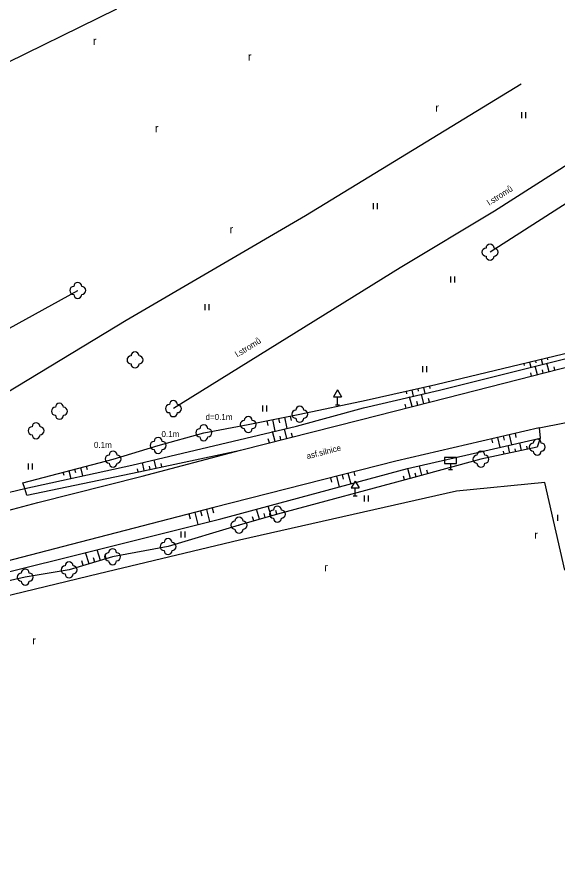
# Model space of a CAD drawing. Extents: x -544674 to -541478, y -1199076 to -1195527.
# Drawn here: x -543143.9 to -543076.3, y -1198278.6 to -1198172.4 of the extents above; entities that cross this region are included whole.
import ezdxf

# ---------------------------------------------------------------- set-up
doc = ezdxf.new("R2010")
doc.units = 0
for name, color, linetype in [('POMOC_POPIS', 7, 'Continuous'), ('ROZHRANÍ_PLOCH', 7, 'Continuous'), ('VÝŠKOPIS', 7, 'Continuous'), ('ZELEŇ', 7, 'Continuous'), ('ZN_DOPLŇKOVÉ', 7, 'Continuous'), ('ZN_KULTUR', 7, 'Continuous')]:
    doc.layers.add(name, color=color, linetype=linetype)

msp = doc.modelspace()

# ---------------------------------------------------------------- linework, layer by layer
at = {"layer": 'ROZHRANÍ_PLOCH'}
for points in [[(-543305.81, -1198268.45), (-543287.03, -1198267.34), (-543281.63, -1198266.75), (-543272.62, -1198265.24), (-543259.93, -1198262.7), (-543247.53, -1198260.01), (-543230.83, -1198255.93), (-543205.96, -1198249.68), (-543192.48, -1198246.27), (-543169.15, -1198240.29), (-543156.96, -1198237.13), (-543145.63, -1198234.19), (-543141.25, -1198233.03), (-543128.24, -1198229.71), (-543115.97, -1198226.49), (-543101.02, -1198222.68), (-543090.25, -1198219.95), (-543068.96, -1198214.5), (-543040.35, -1198207.27)], [(-543078.71, -1198223.67), (-543075.55, -1198223.08), (-543073.66, -1198223.03), (-543073.06, -1198223.47)], [(-543078.71, -1198223.67), (-543096.57, -1198227.83), (-543119.29, -1198233.63), (-543137.11, -1198238.27), (-543169.75, -1198246.75), (-543192.65, -1198252.45), (-543215.76, -1198258.44), (-543245.09, -1198265.54), (-543253.15, -1198267.41), (-543264.32, -1198269.8), (-543273.65, -1198271.57), (-543287.74, -1198273.53), (-543300.36, -1198274.19)]]:
    msp.add_lwpolyline(points, dxfattribs=at)
at = {"layer": 'VÝŠKOPIS'}
for points in [[(-543142.63, -1198232.09), (-543142.88, -1198231.28), (-543143.14, -1198230.54), (-543131.88, -1198227.59), (-543126.25, -1198225.89), (-543120.55, -1198224.3), (-543115, -1198223.27), (-543108.58, -1198221.98), (-543100.29, -1198220.25), (-543091.61, -1198218.29), (-543068.38, -1198212.71), (-543040.75, -1198205.87), (-543040.68, -1198206.39), (-543040.35, -1198207.27)], [(-543142.88, -1198231.28), (-543129.55, -1198228.33), (-543108.99, -1198223.46), (-543100.64, -1198221.19), (-543091.14, -1198218.96), (-543068.67, -1198213.36), (-543040.68, -1198206.39)], [(-543079.89, -1198215.47), (-543079.73, -1198216.12)], [(-543079.16, -1198215.3), (-543079.1, -1198215.55)], [(-543078.43, -1198215.12), (-543078.28, -1198215.75)], [(-543077.7, -1198214.95), (-543077.64, -1198215.2)], [(-543080.62, -1198215.65), (-543080.56, -1198215.91)], [(-543078.91, -1198217.05), (-543079.19, -1198215.98)], [(-543078.19, -1198216.86), (-543078.29, -1198216.44)], [(-543077.46, -1198216.68), (-543077.73, -1198215.62)], [(-543076.73, -1198216.49), (-543076.84, -1198216.07)], [(-543079.64, -1198217.23), (-543079.75, -1198216.81)], [(-543093.12, -1198218.63), (-543092.95, -1198219.38)], [(-543092.39, -1198218.47), (-543092.32, -1198218.76)], [(-543095.31, -1198219.13), (-543095.24, -1198219.43)], [(-543094.55, -1198221.04), (-543094.86, -1198219.83)], [(-543094.58, -1198218.96), (-543094.41, -1198219.73)], [(-543093.85, -1198218.8), (-543093.78, -1198219.1)], [(-543093.1, -1198220.67), (-543093.4, -1198219.49)], [(-543095.28, -1198221.23), (-543095.4, -1198220.74)], [(-543093.83, -1198220.86), (-543093.95, -1198220.38)], [(-543092.37, -1198220.49), (-543092.49, -1198220.02)], [(-543112.7, -1198222.81), (-543112.58, -1198223.39)], [(-543111.96, -1198222.66), (-543111.67, -1198224.1)], [(-543111.23, -1198222.51), (-543111.11, -1198223.08)], [(-543110.49, -1198222.36), (-543110.21, -1198223.75)], [(-543109.76, -1198222.22), (-543109.65, -1198222.76)], [(-543078.71, -1198223.67), (-543078.55, -1198224.98), (-543078.93, -1198226.1), (-543085.96, -1198227.61), (-543094.34, -1198229.89), (-543111.37, -1198234.47), (-543116.16, -1198235.85), (-543125.01, -1198238.52), (-543131.94, -1198239.79), (-543137.37, -1198241.43), (-543142.84, -1198242.34), (-543149.33, -1198243.78)], [(-543110.19, -1198225.02), (-543110.5, -1198223.82)], [(-543300.33, -1198275.71), (-543287.42, -1198274.93), (-543273.98, -1198273.27), (-543263.19, -1198271.16), (-543253.24, -1198268.92), (-543244.35, -1198266.6), (-543214.79, -1198259.43), (-543191.44, -1198253.57), (-543168.88, -1198247.61), (-543136.22, -1198239.51), (-543118.41, -1198235.04), (-543095.11, -1198228.78), (-543078.55, -1198224.98)], [(-543112.37, -1198225.57), (-543112.5, -1198225.08)], [(-543111.65, -1198225.39), (-543111.96, -1198224.16)], [(-543110.92, -1198225.2), (-543111.04, -1198224.72)], [(-543109.47, -1198224.83), (-543109.59, -1198224.36)], [(-543084.63, -1198225.05), (-543084.52, -1198225.55)], [(-543083.9, -1198224.88), (-543083.61, -1198226.14)], [(-543083.17, -1198224.71), (-543083.05, -1198225.21)], [(-543082.44, -1198224.54), (-543082.15, -1198225.81)], [(-543081.71, -1198224.37), (-543081.59, -1198224.88)], [(-543082.35, -1198226.83), (-543082.55, -1198225.9)], [(-543080.88, -1198226.52), (-543081.09, -1198225.56)], [(-543080.15, -1198226.36), (-543080.23, -1198225.97)], [(-543142.63, -1198232.09), (-543128.68, -1198229.18), (-543115.97, -1198226.49)], [(-543083.08, -1198226.99), (-543083.16, -1198226.62)], [(-543081.62, -1198226.68), (-543081.7, -1198226.3)], [(-543127.99, -1198229.03), (-543128.21, -1198228.01)], [(-543126.52, -1198228.72), (-543126.75, -1198227.67)], [(-543125.79, -1198228.57), (-543125.88, -1198228.14)], [(-543138.14, -1198229.23), (-543138.04, -1198229.61)], [(-543137.42, -1198229.04), (-543137.16, -1198230.01)], [(-543136.69, -1198228.85), (-543136.58, -1198229.25)], [(-543135.96, -1198228.66), (-543135.69, -1198229.69)], [(-543135.24, -1198228.47), (-543135.13, -1198228.89)], [(-543128.73, -1198229.19), (-543128.81, -1198228.79)], [(-543127.26, -1198228.88), (-543127.35, -1198228.46)], [(-543102.56, -1198229.36), (-543102.22, -1198230.69)], [(-543101.83, -1198229.17), (-543101.7, -1198229.7)], [(-543094.76, -1198230), (-543095.09, -1198228.78)], [(-543094.04, -1198229.81), (-543094.17, -1198229.33)], [(-543093.32, -1198229.61), (-543093.64, -1198228.44)], [(-543092.59, -1198229.41), (-543092.72, -1198228.96)], [(-543104.74, -1198229.92), (-543104.6, -1198230.46)], [(-543104.01, -1198229.73), (-543103.67, -1198231.08)], [(-543103.29, -1198229.54), (-543103.15, -1198230.08)], [(-543095.49, -1198230.2), (-543095.62, -1198229.71)], [(-543112.16, -1198234.7), (-543112.51, -1198233.46)], [(-543122.41, -1198234.44), (-543122.25, -1198235.04)], [(-543121.68, -1198234.25), (-543121.29, -1198235.76)], [(-543120.96, -1198234.06), (-543120.8, -1198234.67)], [(-543120.23, -1198233.88), (-543119.84, -1198235.4)], [(-543119.51, -1198233.69), (-543119.35, -1198234.3)], [(-543113.6, -1198235.11), (-543113.96, -1198233.85)], [(-543112.88, -1198234.9), (-543113.02, -1198234.4)], [(-543111.44, -1198234.49), (-543111.58, -1198234)], [(-543114.32, -1198235.32), (-543114.47, -1198234.81)], [(-543133.44, -1198240.24), (-543133.85, -1198238.91)], [(-543134.88, -1198240.68), (-543135.3, -1198239.28)], [(-543134.16, -1198240.46), (-543134.33, -1198239.92)], [(-543132.73, -1198240.03), (-543132.88, -1198239.51)], [(-543135.6, -1198240.89), (-543135.77, -1198240.32)]]:
    msp.add_lwpolyline(points, dxfattribs=at)
at = {"layer": 'ZELEŇ'}
for points in [[(-543131.46, -1198171.38), (-543147.42, -1198179.22), (-543163.22, -1198188.16)], [(-543268.42, -1198213.5), (-543284.71, -1198220.73), (-543286.6, -1198222.69), (-543287.27, -1198226.37), (-543285.42, -1198237.78), (-543282.82, -1198246.6), (-543282.23, -1198253.38), (-543281.58, -1198260.61), (-543280.91, -1198262.28), (-543276.7, -1198262.28), (-543257.57, -1198258.22), (-543230.23, -1198250.96), (-543217.95, -1198248.16), (-543208.84, -1198246.19), (-543196.29, -1198243.16), (-543184.98, -1198239.31), (-543170.26, -1198234.36), (-543155.85, -1198226.05), (-543146.56, -1198220.12), (-543130.23, -1198210.22), (-543107.84, -1198197.15), (-543080.94, -1198180.71)], [(-543064.97, -1198184.3), (-543084.25, -1198196.62), (-543096.05, -1198203.68), (-543124.35, -1198221.29)], [(-543063.95, -1198188.37), (-543084.83, -1198201.74)], [(-543209.95, -1198244.79), (-543172.83, -1198226.67), (-543136.29, -1198206.52)], [(-543075.5, -1198241.48), (-543077.98, -1198230.53), (-543089, -1198231.59), (-543116.11, -1198237.7), (-543133.65, -1198241.93), (-543167.02, -1198250.02), (-543188.93, -1198255.7), (-543211.29, -1198261.26), (-543234.99, -1198267.13), (-543253.33, -1198271.2), (-543261.11, -1198272.92), (-543275.52, -1198275.61), (-543286.14, -1198277.35), (-543300.17, -1198278.55)]]:
    msp.add_lwpolyline(points, dxfattribs=at)
for centre in [(-543084.83, -1198201.74), (-543136.29, -1198206.52), (-543129.14, -1198215.2), (-543138.57, -1198221.62), (-543124.35, -1198221.29), (-543108.58, -1198221.98), (-543141.49, -1198224.05), (-543115, -1198223.27), (-543120.55, -1198224.3), (-543126.25, -1198225.89), (-543078.93, -1198226.1), (-543131.88, -1198227.59), (-543085.96, -1198227.61), (-543111.37, -1198234.47), (-543116.16, -1198235.85), (-543125.01, -1198238.52), (-543131.94, -1198239.79), (-543137.37, -1198241.43), (-543142.84, -1198242.34)]:
    msp.add_circle(centre, 0.0005, dxfattribs=at)
for centre, start, end in [((-543085.33, -1198201.74), 89.99999, 269.99999), ((-543084.83, -1198201.24), 0, 179.99999), ((-543084.33, -1198201.74), 270, 89.99999), ((-543084.83, -1198202.24), 179.99999, 359.99999), ((-543136.79, -1198206.52), 89.99999, 269.99999), ((-543136.29, -1198206.02), 0, 179.99999), ((-543135.79, -1198206.52), 270, 89.99999), ((-543136.29, -1198207.02), 179.99999, 359.99999), ((-543129.14, -1198214.7), 0, 179.99999), ((-543129.64, -1198215.2), 89.99999, 269.99999), ((-543128.64, -1198215.2), 270, 89.99999), ((-543129.14, -1198215.7), 179.99999, 359.99999), ((-543138.57, -1198221.12), 0, 179.99999), ((-543124.85, -1198221.29), 89.99999, 269.99999), ((-543124.35, -1198220.79), 0, 179.99999), ((-543123.85, -1198221.29), 270, 89.99999), ((-543139.07, -1198221.62), 89.99999, 269.99999), ((-543138.07, -1198221.62), 270, 89.99999), ((-543124.35, -1198221.79), 179.99999, 359.99999), ((-543109.08, -1198221.98), 89.99999, 269.99999), ((-543108.58, -1198221.48), 0, 179.99999), ((-543108.08, -1198221.98), 270, 89.99999), ((-543138.57, -1198222.12), 179.99999, 359.99999), ((-543115.5, -1198223.27), 89.99999, 269.99999), ((-543115, -1198222.77), 0, 179.99999), ((-543114.5, -1198223.27), 270, 89.99999), ((-543108.58, -1198222.48), 179.99999, 359.99999), ((-543141.99, -1198224.05), 89.99999, 269.99999), ((-543141.49, -1198223.55), 0, 179.99999), ((-543140.99, -1198224.05), 270, 89.99999), ((-543121.05, -1198224.3), 89.99999, 269.99999), ((-543120.55, -1198223.8), 0, 179.99999), ((-543120.05, -1198224.3), 270, 89.99999), ((-543115, -1198223.77), 179.99999, 359.99999), ((-543141.49, -1198224.55), 179.99999, 359.99999), ((-543126.25, -1198225.39), 0, 179.99999), ((-543120.55, -1198224.8), 179.99999, 359.99999), ((-543078.93, -1198225.6), 0, 179.99999), ((-543126.75, -1198225.89), 89.99999, 269.99999), ((-543125.75, -1198225.89), 270, 89.99999), ((-543079.43, -1198226.1), 89.99999, 269.99999), ((-543078.43, -1198226.1), 270, 89.99999), ((-543132.38, -1198227.59), 89.99999, 269.99999), ((-543131.88, -1198227.09), 0, 179.99999), ((-543131.38, -1198227.59), 270, 89.99999), ((-543126.25, -1198226.39), 179.99999, 359.99999), ((-543086.46, -1198227.61), 89.99999, 269.99999), ((-543085.96, -1198227.11), 0, 179.99999), ((-543085.46, -1198227.61), 270, 89.99999), ((-543078.93, -1198226.6), 179.99999, 359.99999), ((-543131.88, -1198228.09), 179.99999, 359.99999), ((-543085.96, -1198228.11), 179.99999, 359.99999), ((-543111.37, -1198233.97), 0, 179.99999), ((-543111.87, -1198234.47), 89.99999, 269.99999), ((-543110.87, -1198234.47), 270, 89.99999), ((-543116.66, -1198235.85), 89.99999, 269.99999), ((-543116.16, -1198235.35), 0, 179.99999), ((-543115.66, -1198235.85), 270, 89.99999), ((-543111.37, -1198234.97), 179.99999, 359.99999), ((-543116.16, -1198236.35), 179.99999, 359.99999), ((-543125.01, -1198238.02), 0, 179.99999), ((-543131.94, -1198239.29), 0, 179.99999), ((-543125.51, -1198238.52), 89.99999, 269.99999), ((-543124.51, -1198238.52), 270, 89.99999), ((-543132.44, -1198239.79), 89.99999, 269.99999), ((-543131.44, -1198239.79), 270, 89.99999), ((-543125.01, -1198239.02), 179.99999, 359.99999), ((-543137.87, -1198241.43), 89.99999, 269.99999), ((-543137.37, -1198240.93), 0, 179.99999), ((-543136.87, -1198241.43), 270, 89.99999), ((-543131.94, -1198240.29), 179.99999, 359.99999), ((-543143.34, -1198242.34), 89.99999, 269.99999), ((-543142.84, -1198241.84), 0, 179.99999), ((-543142.34, -1198242.34), 270, 89.99999), ((-543137.37, -1198241.93), 179.99999, 359.99999), ((-543142.84, -1198242.84), 179.99999, 359.99999)]:
    msp.add_arc(centre, 0.5, start, end, dxfattribs=at)
at = {"layer": 'ZN_DOPLŇKOVÉ'}
for p, q in [((-543103.86, -1198218.954), (-543104.36, -1198219.82)), ((-543104.36, -1198219.82), (-543103.36, -1198219.82)), ((-543103.86, -1198218.954), (-543103.36, -1198219.82)), ((-543103.86, -1198220.82), (-543103.86, -1198219.82)), ((-543104.11, -1198220.82), (-543103.61, -1198220.82)), ((-543089.78, -1198228.16), (-543089.78, -1198228.91)), ((-543090.03, -1198228.91), (-543089.53, -1198228.91)), ((-543101.67, -1198230.334), (-543102.17, -1198231.2)), ((-543101.67, -1198230.334), (-543101.17, -1198231.2)), ((-543102.17, -1198231.2), (-543101.17, -1198231.2)), ((-543101.67, -1198232.2), (-543101.67, -1198231.2)), ((-543101.92, -1198232.2), (-543101.42, -1198232.2))]:
    msp.add_line(p, q, dxfattribs=at)
msp.add_lwpolyline([(-543090.53, -1198228.16), (-543089.03, -1198228.16), (-543089.03, -1198227.41), (-543090.53, -1198227.41)], close=True, dxfattribs=at)
msp.add_lwpolyline([(-543146.94, -1198232.22), (-543142.88, -1198231.28)], dxfattribs=at)
at = {"layer": 'ZN_KULTUR'}
for p, q in [((-543080.87, -1198185.005), (-543080.87, -1198184.255)), ((-543080.37, -1198185.005), (-543080.37, -1198184.255)), ((-543099.36, -1198196.385), (-543099.36, -1198195.635)), ((-543098.86, -1198196.385), (-543098.86, -1198195.635)), ((-543089.71, -1198205.525), (-543089.71, -1198204.775)), ((-543089.21, -1198205.525), (-543089.21, -1198204.775)), ((-543120.4, -1198209.005), (-543120.4, -1198208.255)), ((-543119.9, -1198209.005), (-543119.9, -1198208.255)), ((-543093.23, -1198216.715), (-543093.23, -1198215.965)), ((-543092.73, -1198216.715), (-543092.73, -1198215.965)), ((-543113.2, -1198221.655), (-543113.2, -1198220.905)), ((-543112.7, -1198221.655), (-543112.7, -1198220.905)), ((-543142.42, -1198228.905), (-543142.42, -1198228.155)), ((-543141.92, -1198228.905), (-543141.92, -1198228.155)), ((-543100.49, -1198232.875), (-543100.49, -1198232.125)), ((-543099.99, -1198232.875), (-543099.99, -1198232.125)), ((-543076.35, -1198235.295), (-543076.35, -1198234.545)), ((-543123.38, -1198237.405), (-543123.38, -1198236.655)), ((-543122.88, -1198237.405), (-543122.88, -1198236.655))]:
    msp.add_line(p, q, dxfattribs=at)

# ---------------------------------------------------------------- texts
at = {"layer": 'POMOC_POPIS'}
msp.add_text('asf.silnice', height=0.75, rotation=14.32071, dxfattribs=at).set_placement((-543107.63, -1198227.6))
at = {"layer": 'ZELEŇ'}
for rotation, p in [(32.57875, (-543084.91, -1198195.94)), (31.89241, (-543116.35, -1198214.9))]:
    msp.add_text('l.stromů', height=0.75, rotation=rotation, dxfattribs=at).set_placement(p)
for s, p in [('d=0.1m', (-543120.34, -1198222.7)), ('0.1m', (-543125.84, -1198224.84)), ('0.1m', (-543134.27, -1198226.19))]:
    msp.add_text(s, height=0.75, dxfattribs=at).set_placement(p)
at = {"layer": 'ZN_KULTUR'}
for p in [(-543134.398, -1198175.852), (-543115.048, -1198177.812), (-543091.648, -1198184.192), (-543126.648, -1198186.752), (-543117.338, -1198199.392), (-543079.298, -1198237.552), (-543105.528, -1198241.602), (-543141.968, -1198250.752)]:
    msp.add_text('r', height=1, dxfattribs=at).set_placement(p)

doc.saveas('drawing.dxf')
